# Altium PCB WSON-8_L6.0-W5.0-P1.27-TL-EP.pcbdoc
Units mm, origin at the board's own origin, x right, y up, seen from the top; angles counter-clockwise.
Board outline 20.29 x 17.81 mm, 2 copper layers (Top Layer, Bottom Layer), stack 0 mm thick; 1 components, 0 nets, 9 pads, 0 vias.
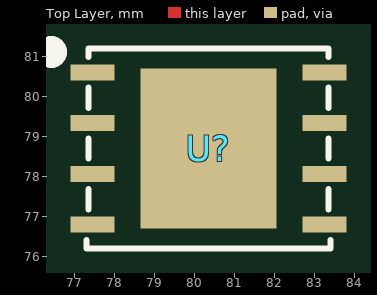
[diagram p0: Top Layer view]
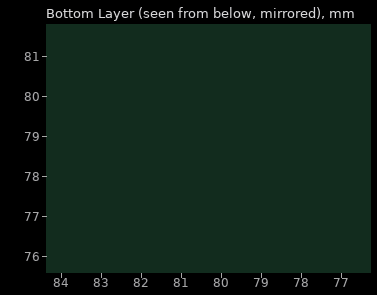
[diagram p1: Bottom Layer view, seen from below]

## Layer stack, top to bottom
Top Layer: signal copper (thickness not stored)
Bottom Layer: signal copper (thickness not stored)

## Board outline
90.137,69.85 69.85,69.85 69.85,87.663 90.137,87.663

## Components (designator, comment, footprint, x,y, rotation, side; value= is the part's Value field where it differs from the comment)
U? "" WSON-8_L6.0-W5.0-P1.27-TL-EP 80.337,78.7 r0 top

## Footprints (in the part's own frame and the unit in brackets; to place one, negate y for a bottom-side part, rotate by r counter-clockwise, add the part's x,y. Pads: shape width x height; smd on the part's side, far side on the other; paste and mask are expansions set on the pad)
WSON-8_L6.0-W5.0-P1.27-TL-EP [mm]
  rect 1.1x0.4 smd paste-100 mask+0.05: 1(-2.9,1.905) 2(-2.9,0.635) 3(-2.9,-0.635) 4(-2.9,-1.905) 5(2.9,-1.905) 6(2.9,-0.635) 7(2.9,0.635) 8(2.9,1.905)
  rect 3.4x4 smd paste-100 mask+0.05: 9(0,0)
  silkscreen extent -4.14,-2.5 3.05,2.61

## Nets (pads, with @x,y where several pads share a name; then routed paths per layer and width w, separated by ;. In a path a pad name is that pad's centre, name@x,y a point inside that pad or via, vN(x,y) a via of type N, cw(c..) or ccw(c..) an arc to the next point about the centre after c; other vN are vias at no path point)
pads on no net: U?.1 U?.2 U?.3 U?.4 U?.5 U?.6 U?.7 U?.8 U?.9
